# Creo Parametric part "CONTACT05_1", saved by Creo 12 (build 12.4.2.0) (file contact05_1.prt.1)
Units: Custom; MM, KILOGRAM, SECS

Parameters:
  PTC_WM_ITERATION = "0"
  PTC_WM_VERSION = "-.0"
  PTC_WM_LIFECYCLE_STATE = "In Work"
  PTC_WM_LIFECYCLE = "MO_CADDocument"
  PTC_WM_CREATED_BY = "Maximilian Roepper (Z0017RMS: MO)"
  PTC_WM_CREATED_ON = "18-Sep-26 11:36:42 AM"
  PTC_WM_MODIFIED_BY = "Maximilian Roepper (Z0017RMS: MO)"
  PTC_WM_MODIFIED_ON = "18-Sep-26 11:36:46 AM"
  PDMLINKNUMBER = "PDM000071455077"
  PTC_WM_NAME = "contact05_1.prt"
  PTC_WM_NUMBER = "PDM000071455077"

Other parameters: WEIGHT, WEIGHT_FACTOR, WEIGHT_ADD, _MASS_TEMP, _DIFF_TEMP, MC_ERRORS, SUPPLIER

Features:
  1. coordinate system
  2. datum plane "PRT_YZ"
  3. datum plane "PRT_XY"
  4. datum plane "PRT_XZ"
  5. coordinate system
  6. datum axis
  7. datum axis
  8. datum axis
  9. coordinate system
  10. imported feature

Other named items: PRT, SIEMENS_MO, DRW_VIEW_ORG, PRT_X, PRT_Y, PRT_Z, CS0, ROUGH_GROB

Layers: 00_STD_CSYS-KSYS, 01_STD_PLANES-EBENEN, 02_STD_AXES-ACHSEN, 03_STD_CSYS-KSYS, 24_IMPORT_FEAT-IMPORT_KE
